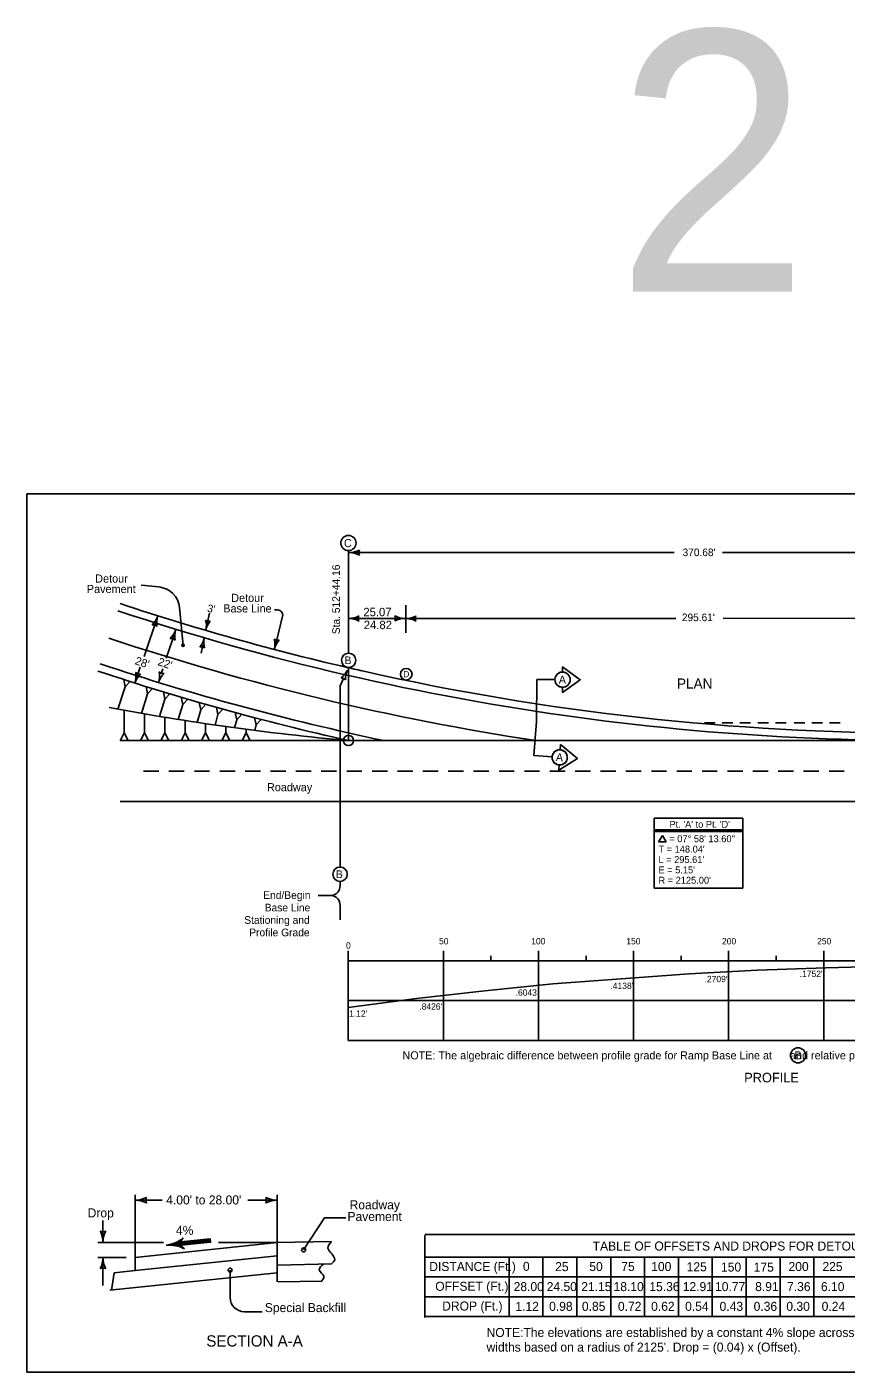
# Model space of a CAD drawing. Extents: x 10133 to 81668, y 4099 to 11018.
# Drawn here: x 13733 to 15616, y 7924 to 11018 of the extents above; entities that cross this region are included whole.
import ezdxf

# ---------------------------------------------------------------- set-up
doc = ezdxf.new("R2010")
doc.units = 0
for name, color, linetype in [('Default', 7, 'Continuous'), ('dsnCellElements', 7, 'Continuous'), ('Level 1', 7, 'Continuous'), ('Level 10', 7, 'Continuous'), ('Level 12', 7, 'Continuous'), ('Level 4', 7, 'Continuous'), ('Level 5', 7, 'Continuous'), ('SheetAddendum', 7, 'Continuous'), ('SheetBorder', 7, 'Continuous'), ('SheetText', 7, 'Continuous'), ('ShtPlotIdentification', 7, 'Continuous')]:
    doc.layers.add(name, color=color, linetype=linetype)

msp = doc.modelspace()

# ---------------------------------------------------------------- linework, layer by layer
at = {"layer": 'Default'}
for p, q in [((14471.7, 9376.6), (14471.7, 9544.2)), ((14471.7, 9544.2), (14471.7, 9376.6)), ((14471.7, 9376.6), (16078.7, 9376.6)), ((14471.7, 9376.6), (16078.7, 9376.6))]:
    msp.add_line(p, q, dxfattribs=at)
for centre, radius, start, end in [((15786.9, 15230.7), 5836.7, 251.62748, 257.33821), ((15786.9, 15230.7), 5854, 251.62748, 272.85748), ((15786.9, 15230.7), 5920.4, 251.62748, 261.4196), ((15786.9, 15230.7), 6000.1, 251.62748, 257.33821), ((15786.9, 15230.7), 5982.7, 251.62748, 258.10097), ((15786.9, 15230.7), 5836.7, 256.97753, 257.33821), ((15786.9, 15230.7), 5836.7, 257.33821, 270), ((15786.9, 15230.7), 5836.7, 257.33821, 270), ((15002.9, 15258.6), 5905.9, 259.45431, 264.83954)]:
    msp.add_arc(centre, radius, start, end, dxfattribs=at)
at = {"layer": 'dsnCellElements'}
for p, q in [((16087.1, 8240.2), (14647.3, 8240.2)), ((14647.3, 8237.9), (14647.3, 8049.7)), ((16087.1, 8188.2), (14647.3, 8188.2)), ((14841.2, 8188.2), (14841.2, 8052)), ((14919, 8188.2), (14919, 8188.2)), ((14919, 8188.2), (14919, 8052)), ((14919.3, 8188.2), (14919.3, 8188.2)), ((14919.4, 8188.2), (14919.4, 8188.2)), ((14919.6, 8188.2), (14919.6, 8188.2)), ((14996.9, 8188.2), (14996.9, 8052)), ((14996.9, 8188.2), (14996.9, 8188.2)), ((14996.9, 8188.2), (14996.9, 8052)), ((14997.1, 8188.2), (14997.1, 8188.2)), ((14997.3, 8188.2), (14997.3, 8188.2)), ((14997.5, 8188.2), (14997.5, 8188.2)), ((15074.8, 8188.2), (15074.8, 8052)), ((15152.7, 8188.2), (15152.7, 8052)), ((15230.5, 8188.2), (15230.5, 8052)), ((15308.4, 8188.2), (15308.4, 8052)), ((15386.3, 8188.2), (15386.3, 8052)), ((15464.1, 8188.2), (15464.1, 8052)), ((15542, 8188.2), (15542, 8052)), ((16087.1, 8142.8), (14647.3, 8142.8)), ((16087.1, 8097.4), (14647.3, 8097.4)), ((16087.1, 8052), (14647.3, 8052))]:
    msp.add_line(p, q, dxfattribs=at)
at = {"layer": 'Level 1'}
for p, q in [((13941.9, 9448.7), (13958.3, 9500.2)), ((13958.3, 9500.2), (13955.5, 9517)), ((13958.3, 9500.2), (13970.3, 9512.2)), ((14009.7, 9484.1), (14006.7, 9500.8)), ((13995.8, 9439.1), (14009.7, 9484.1)), ((14009.7, 9484.1), (14021.6, 9496.2)), ((14037.7, 9432), (14049.7, 9471.9)), ((14049.7, 9471.9), (14046.6, 9488.6)), ((14049.7, 9471.9), (14061.5, 9484.1)), ((14090.7, 9459.6), (14087.5, 9476.3)), ((14090.7, 9459.6), (14102.5, 9471.9)), ((13956.3, 9446.1), (13956.3, 9394.5)), ((14003, 9437.9), (14003, 9394.5)), ((14080.6, 9425.1), (14090.7, 9459.6)), ((14123.9, 9418.4), (14132.2, 9447.6)), ((14132.2, 9447.6), (14128.9, 9464.3)), ((14132.2, 9447.6), (14143.9, 9460)), ((14171.8, 9436.4), (14168.3, 9453.1)), ((14171.8, 9436.4), (14183.3, 9448.9)), ((14214.8, 9424.6), (14211.3, 9441.2)), ((14214.8, 9424.6), (14226.3, 9437.1)), ((14049.7, 9430.1), (14049.7, 9394.5)), ((14096.4, 9422.6), (14096.4, 9394.5)), ((14143.1, 9415.5), (14143.1, 9394.5)), ((14165, 9412.4), (14171.8, 9436.4)), ((14189.8, 9408.9), (14189.8, 9394.5)), ((14209.8, 9406.1), (14214.8, 9424.6)), ((14259.6, 9412.7), (14255.9, 9429.3)), ((14256.3, 9400), (14259.6, 9412.7)), ((14259.6, 9412.7), (14271, 9425.3)), ((13956.3, 9394.5), (13946.7, 9376)), ((13956.3, 9394.5), (13965.6, 9376.6)), ((14003, 9394.5), (13993.7, 9376.6)), ((14003, 9394.5), (14012.3, 9376.6)), ((14049.7, 9394.5), (14040.4, 9376.6)), ((14049.7, 9394.5), (14059, 9376.6)), ((14096.4, 9394.5), (14086.8, 9376)), ((14096.4, 9394.5), (14105.7, 9376.6)), ((14143.1, 9394.5), (14133.8, 9376.6)), ((14143.1, 9394.5), (14152.4, 9376.6)), ((14189.8, 9394.5), (14180.5, 9376.6)), ((14189.8, 9394.5), (14199, 9376.6)), ((14236.5, 9394.5), (14227.2, 9376.6)), ((14236.5, 9402.6), (14236.5, 9394.5)), ((14236.5, 9394.5), (14245.7, 9376.6))]:
    msp.add_line(p, q, dxfattribs=at)
at = {"layer": 'Level 10'}
for p, q in [((14471.7, 9577.7), (14471.7, 9813.5)), ((14309, 9677.2), (14301.8, 9677.2)), ((14301.8, 9586.2), (14320.3, 9662.8)), ((14471.7, 9544.2), (14471.7, 9544.7)), ((14452.5, 9502.4), (14460.5, 9519.2)), ((14452.5, 9502.4), (14452.5, 9085.7)), ((15174.7, 9198), (15174.7, 9037.3)), ((15174.7, 9198), (15378.3, 9198)), ((15378.3, 9037.3), (15378.3, 9198)), ((15174.7, 9171), (15378.3, 9171)), ((15174.7, 9167.1), (15378.3, 9167.1)), ((15184.6, 9143.4), (15193.6, 9158.3)), ((15202.5, 9143.4), (15184.6, 9143.4)), ((15193.6, 9158.3), (15202.5, 9143.4)), ((14452.5, 9043.5), (14452.5, 9052.7)), ((15174.7, 9037.3), (15378.3, 9037.3)), ((14402.5, 9020.3), (14432.1, 9020.3)), ((14452.5, 8997.1), (14452.5, 8964.5)), ((13981.3, 8187.9), (13981.3, 8331.9)), ((14308.1, 8222.1), (14308.1, 8331.9)), ((14199.8, 8158.5), (14199.8, 8095.4)), ((14273.7, 8062.9), (14232.3, 8062.9))]:
    msp.add_line(p, q, dxfattribs=at)
for centre, radius in [((14471.7, 9831), 17.5), ((14091.5, 9595.6), 2.42), ((14091.5, 9595.6), 2.05), ((14091.5, 9595.6), 1.71), ((14091.5, 9595.6), 1.32), ((14091.5, 9595.6), 1.05), ((14091.5, 9595.6), 0.874), ((14091.5, 9595.6), 0.683), ((14091.5, 9595.6), 0.505), ((14091.5, 9595.6), 0.313), ((14091.5, 9595.6), 0.149), ((14472.3, 9561.2), 16.5), ((14604.6, 9529.3), 13.4), ((14471.7, 9376.6), 11.7), ((14452.5, 9069.2), 16.5)]:
    msp.add_circle(centre, radius, dxfattribs=at)
for centre, radius, start, end in [((14309, 9665.5), 11.7, 346.4041, 90), ((14152.2, 9669.3), 18.1, 240.459, 275.9257), ((14098.4, 9640.5), 46.8, 348.1924, 16.2649), ((14189.9, 9621.4), 46.8, 140.1199, 168.1924), ((14094.5, 9621.9), 46.8, 320.1199, 348.1924), ((14132.2, 9573.9), 18.1, 60.459, 95.9257), ((14186, 9602.7), 46.8, 168.1924, 196.2649), ((14310.5, 9626.8), 19.2, 240.2469, 275.7136), ((14253.3, 9596.5), 49.6, 347.9802, 16.0527), ((14350.3, 9575.8), 49.6, 139.9077, 167.9802), ((14426.8, 9559), 47.3, 306.4802, 334.5527), ((14512.3, 9518.3), 47.3, 154.5527, 182.6252), ((14452.5, 9502.8), 18.3, 46.8193, 82.286), ((14430.5, 9042.3), 22, 274.0563, 3.2919), ((14430.5, 8998.4), 22, 356.7081, 85.9437), ((14232.3, 8095.4), 32.4, 180, 270)]:
    msp.add_arc(centre, radius, start, end, dxfattribs=at)
at = {"layer": 'Level 12'}
for centre in [(14368.8, 8205.1), (14199.8, 8158.5)]:
    msp.add_circle(centre, 4.6, dxfattribs=at)
at = {"layer": 'Level 4'}
for p, q in [((14904.6, 9517.1), (14903.9, 9420.4)), ((14904.6, 9517.1), (14946.6, 9516.8)), ((14903.9, 9420.4), (14898.1, 9342.4)), ((14898.1, 9342.4), (14940, 9339.3))]:
    msp.add_line(p, q, dxfattribs=at)
for points in [[(14964.2, 9534.2), (14964.3, 9545.9), (15004.9, 9516.4), (14963.9, 9487.5), (14964, 9499.2)], [(14964.2, 9534.2), (14964.2, 9534.2), (14964.2, 9534.2)], [(14958.8, 9355.5), (14959.7, 9367.2), (14998.3, 9335), (14955.4, 9308.9), (14956.2, 9320.6)], [(14958.8, 9355.5), (14958.8, 9355.5), (14958.8, 9355.5)]]:
    msp.add_lwpolyline(points, dxfattribs=at)
for centre, radius in [((14964.1, 9516.7), 17.5), ((14957.5, 9338), 17.5), ((15505.5, 8652.6), 17.4)]:
    msp.add_circle(centre, radius, dxfattribs=at)
for centre, start, end in [((14964.1, 9516.7), 89.5971, 269.5988), ((14964.1, 9516.7), 269.5988, 89.5971), ((14957.5, 9338), 85.783, 265.7846), ((14957.5, 9338), 265.7846, 85.783)]:
    msp.add_arc(centre, 17.5, start, end, dxfattribs=at)
at = {"layer": 'Level 5'}
for p, q in [((15314.7, 9417.3), (15290.2, 9417.3)), ((15355.5, 9417.3), (15331, 9417.3)), ((15396.4, 9417.3), (15371.9, 9417.3)), ((15437.2, 9417.3), (15412.7, 9417.3)), ((15478.1, 9417.3), (15453.6, 9417.3)), ((15520.9, 9417.4), (15496.4, 9417.4)), ((15561.7, 9417.4), (15537.2, 9417.4)), ((15602.6, 9417.4), (15578.1, 9417.4)), ((14455.2, 9376.6), (13946.7, 9376.6)), ((14035.9, 9306.5), (14000.8, 9306.5)), ((14094.2, 9306.5), (14059.2, 9306.5)), ((14152.6, 9306.5), (14117.6, 9306.5)), ((14211, 9306.5), (14175.9, 9306.5)), ((14269.3, 9306.5), (14234.3, 9306.5)), ((14327.7, 9306.5), (14292.7, 9306.5)), ((14386.1, 9306.5), (14351, 9306.5)), ((14444.4, 9306.5), (14409.4, 9306.5)), ((14502.8, 9306.5), (14467.8, 9306.5)), ((14561.2, 9306.5), (14526.1, 9306.5)), ((14619.5, 9306.5), (14584.5, 9306.5)), ((14677.9, 9306.5), (14642.9, 9306.5)), ((14736.3, 9306.5), (14701.2, 9306.5)), ((14794.6, 9306.5), (14759.6, 9306.5)), ((14853, 9306.5), (14818, 9306.5)), ((14911.4, 9306.5), (14876.3, 9306.5)), ((14969.7, 9306.5), (14934.7, 9306.5)), ((15028.1, 9306.5), (14993.1, 9306.5)), ((15086.5, 9306.5), (15051.4, 9306.5)), ((15144.8, 9306.5), (15109.8, 9306.5)), ((15203.2, 9306.5), (15168.2, 9306.5)), ((15261.6, 9306.5), (15226.5, 9306.5)), ((15319.9, 9306.5), (15284.9, 9306.5)), ((15378.3, 9306.5), (15343.3, 9306.5)), ((15436.7, 9306.5), (15401.6, 9306.5)), ((15495, 9306.5), (15460, 9306.5)), ((15553.4, 9306.5), (15518.4, 9306.5)), ((15611.8, 9306.5), (15576.7, 9306.5)), ((16078.7, 9236.5), (13947, 9236.5)), ((14471.5, 8687.1), (14471.5, 8892.7)), ((14690.1, 8869.9), (14690.1, 8892.7)), ((14799.4, 8869.9), (14799.4, 8881.3)), ((14908.7, 8687.1), (14908.7, 8892.7)), ((15018, 8869.9), (15018, 8881.3)), ((15127.3, 8687.1), (15127.3, 8892.7)), ((15236.6, 8869.9), (15236.6, 8881.3)), ((15345.9, 8687.1), (15345.9, 8892.7)), ((15455.2, 8869.9), (15455.2, 8881.3)), ((15564.5, 8687.1), (15564.5, 8892.7)), ((14471.5, 8869.9), (16220.3, 8869.9)), ((14690.1, 8869.9), (14690.1, 8687.1)), ((15569.1, 8853.9), (15412.3, 8848.3)), ((15725.9, 8857.6), (15569.1, 8853.9)), ((14941.9, 8816.8), (15098.7, 8828.9)), ((15098.7, 8828.9), (15255.5, 8840)), ((15255.5, 8840), (15412.3, 8848.3)), ((14628.3, 8783.4), (14785.1, 8801)), ((14785.1, 8801), (14941.9, 8816.8)), ((14471.5, 8763), (14628.3, 8783.4)), ((16220.3, 8778.5), (14471.5, 8778.5)), ((14471.5, 8687.1), (16220.3, 8687.1)), ((14368.8, 8205.1), (14416.5, 8279)), ((14416.5, 8279), (14466, 8279)), ((14308.1, 8222.1), (13981.3, 8187.9)), ((14432.7, 8224.6), (14308.1, 8222.1)), ((14308.1, 8131.3), (14308.1, 8222.1)), ((13981.3, 8157.6), (14308.1, 8191.8)), ((13981.3, 8187.9), (13981.3, 8157.6)), ((14432.6, 8172.7), (14309.1, 8170.2)), ((14308.1, 8152.7), (13923.3, 8112.4)), ((13933.1, 8152.6), (13926.8, 8112.8)), ((13981.3, 8157.6), (13933.1, 8152.6)), ((14410.3, 8133.3), (14309.9, 8131.3))]:
    msp.add_line(p, q, dxfattribs=at)
msp.add_lwpolyline([(14308.1, 8222.1), (13981.3, 8187.9), (13981.3, 8157.6), (14308.1, 8191.8)], close=True, dxfattribs=at)
for points in [[(14432.7, 8224.6), (14424.6, 8209.4), (14440.3, 8183), (14432.6, 8172.7)], [(14410.3, 8133.3), (14415.3, 8143.7), (14404.6, 8159.4), (14414.6, 8172.2)]]:
    msp.add_spline(points, degree=3, dxfattribs=at)
at = {"layer": 'SheetAddendum'}
for p, q in [((15221, 9808.9), (14472.9, 9808.9)), ((15331.7, 9808.9), (16079.7, 9808.9)), ((14036.2, 9729.9), (13995.2, 9734.1)), ((14603.7, 9624.8), (14603.7, 9688.1)), ((14001.8, 9570), (14033.3, 9663.4)), ((14091.5, 9595.6), (14083.4, 9682.4)), ((14152.2, 9669.4), (14144.2, 9631)), ((14536.2, 9657.4), (14472.4, 9657.4)), ((14601.5, 9657.6), (14536.2, 9657.4)), ((15224.4, 9657.2), (14606.5, 9657.3)), ((15333.2, 9657.6), (15786.1, 9657.9)), ((14052.8, 9565.8), (14073, 9626.3)), ((14132.9, 9577.7), (14136.9, 9596.3)), ((13980.8, 9508.9), (13992.7, 9545.7)), ((14041.3, 9529.7), (14045.2, 9541.6)), ((14043.2, 8319.4), (13981.3, 8319.4)), ((14308.1, 8319.4), (14240.5, 8319.4)), ((13907.3, 8222.1), (13907.3, 8273)), ((14046.7, 8222.1), (13895.4, 8222.1)), ((14086.7, 8223.6), (14086.7, 8223.6)), ((14086.9, 8219.4), (14154.4, 8226.5)), ((14087.5, 8215.6), (14087.5, 8215.6)), ((14307.7, 8222.1), (14173, 8222.1)), ((13961.1, 8187.9), (13895.4, 8187.9)), ((13907.3, 8123.4), (13907.3, 8187.9))]:
    msp.add_line(p, q, dxfattribs=at)
for points in [[(14088, 8228.5), (14085.6, 8223.6), (14086, 8216.8), (14089, 8211.2), (14078.6, 8214.3), (14066.6, 8216.5), (14063.3, 8217), (14071.5, 8219.5), (14083.3, 8225.1), (14086.7, 8227.5), (14086.9, 8212.9), (14068.3, 8217.2), (14085.2, 8224.4), (14085.6, 8214.4), (14072.8, 8217.8), (14083.8, 8221.8), (14084.9, 8216.1), (14076.8, 8217.9), (14082.6, 8220.2), (14083.2, 8217.5), (14080.3, 8218)], [(14086.7, 8223.3), (14154, 8230.3), (14154.8, 8222.6), (14087.5, 8215.6), (14087, 8222.2), (14153.2, 8229.4), (14153.7, 8223.2), (14088.9, 8216.7), (14088.2, 8221.3), (14152.4, 8228.3), (14152.7, 8224.1), (14089.6, 8217.6), (14089.2, 8220.4), (14151.7, 8227.3), (14151.9, 8225), (14090.4, 8218.7)]]:
    msp.add_lwpolyline(points, dxfattribs=at)
for centre, radius, start, end in [((14473, 9859.8), 50.9, 270, 298.0725), ((14473, 9758), 50.9, 61.9275, 90), ((14515.6, 9808.9), 19.7, 162.2666, 197.7334), ((14030.9, 9677.4), 52.8, 5.3657, 84.2172), ((13986.1, 9678.9), 49.6, 313.6652, 341.7377), ((14080.4, 9647.8), 49.6, 161.7377, 189.8102), ((14472.4, 9707), 49.6, 270, 298.0725), ((14472.4, 9607.8), 49.6, 61.9275, 90), ((14514, 9657.4), 19.2, 162.2666, 197.7334), ((14559.9, 9657.6), 19.2, 342.2666, 17.7333), ((14601.5, 9707.2), 49.6, 241.9275, 270), ((14601.5, 9608), 49.6, 90, 118.0725), ((14603.7, 9706.9), 49.6, 270, 298.0725), ((14603.7, 9607.7), 49.6, 61.9275, 90), ((14645.3, 9657.3), 19.2, 162.2666, 197.7334), ((14020.2, 9623.9), 19.2, 54.0044, 89.4711), ((14027.7, 9647.4), 49.6, 313.6652, 341.7377), ((14122, 9616.3), 49.6, 161.7377, 189.8102), ((14061.8, 9592.4), 19.2, 54.0044, 89.4711), ((13933.7, 9524.5), 49.6, 341.7377, 9.8102), ((13993.8, 9548.4), 19.2, 234.0044, 269.4711), ((13987.9, 9526.1), 49.6, 341.7377, 9.8102), ((14082.1, 9495), 49.6, 133.6652, 161.7377), ((14048, 9550.1), 19.2, 234.0044, 269.4711), ((14027.9, 9493.4), 49.6, 133.6652, 161.7377), ((13981.3, 8374.6), 55.2, 270, 298.0725), ((14027.5, 8319.4), 21.3, 162.2666, 197.7334), ((14261.8, 8319.4), 21.3, 342.2667, 17.7334), ((14308.1, 8374.6), 55.2, 241.9275, 270), ((13981.3, 8264.3), 55.2, 61.9275, 90), ((14308.1, 8264.3), 55.2, 90, 118.0725), ((13907.3, 8268.3), 21.3, 252.2667, 287.7334), ((13852.2, 8222.1), 55.2, 0, 28.0725), ((13962.5, 8222.1), 55.2, 151.9275, 180), ((13852.2, 8187.9), 55.2, 331.9275, 0), ((13962.5, 8187.9), 55.2, 180, 208.0725), ((13907.3, 8141.7), 21.3, 72.2666, 107.7334)]:
    msp.add_arc(centre, radius, start, end, dxfattribs=at)
for centre, major_axis, start_param, end_param in [((14041.6, 8298.8), (8.7, -83.2), 0.029395, 0.553518), ((14100.9, 8220.9), (-1.5, 14.6), 0.553526, 2.588067), ((14059, 8132.4), (8.7, -83.2), 2.588074, 3.112197)]:
    msp.add_ellipse(centre, major_axis=major_axis, ratio=0.985299, start_param=start_param, end_param=end_param, dxfattribs=at)
at = {"layer": 'SheetBorder'}
msp.add_lwpolyline([(13732.5, 9944), (16867.5, 9944), (16867.5, 7924), (13732.5, 7924)], close=True, dxfattribs=at)
at = {"layer": 'ShtPlotIdentification'}
msp.add_line((14471.7, 9376.6), (14455.2, 9376.6), dxfattribs=at)

# ---------------------------------------------------------------- texts
at = {"layer": 'dsnCellElements'}
for s, height, p in [('TABLE OF OFFSETS AND DROPS FOR DETOUR PAVEMENT', 20.766, (15033.3, 8203.6)), ('DISTANCE (Ft.)', 20.766, (14657.6, 8156.5)), ('0', 20.7, (14873, 8156.9)), ('25', 20.75, (14947, 8156.2)), ('50', 20.75, (15025.6, 8156.5)), ('75', 20.75, (15099.1, 8156.5)), ('100', 20.75, (15167.9, 8156.5)), ('125', 20.75, (15249.4, 8155.9)), ('150', 20.75, (15328.4, 8155.3)), ('175', 20.75, (15403.5, 8155.1)), ('200', 20.75, (15483.6, 8156.5)), ('225', 20.75, (15561.6, 8156.5)), ('OFFSET (Ft.)', 20.766, (14671.4, 8111)), ('28.00', 20.75, (14851.6, 8110.3)), ('24.50', 20.75, (14927.6, 8110.3)), ('21.15', 20.75, (15007.1, 8110.3)), ('18.10', 20.75, (15081.3, 8110.3)), ('15.36', 20.75, (15163.6, 8110.3)), ('12.91', 20.75, (15240.4, 8110.3)), ('10.77', 20.75, (15314.7, 8110.3)), ('8.91', 20.75, (15406.9, 8110.3)), ('7.36', 20.75, (15480.2, 8110.3)), ('6.10', 20.75, (15558.2, 8110.3)), ('DROP (Ft.)', 20.77, (14687.3, 8065.6)), ('1.12', 20.75, (14855.6, 8064.8)), ('0.98', 20.75, (14933.2, 8064.9)), ('0.85', 20.75, (15008.6, 8064.9)), ('0.72', 20.75, (15091.4, 8064.9)), ('0.62', 20.75, (15167.7, 8064.9)), ('0.54', 20.75, (15245.9, 8064.9)), ('0.43', 20.75, (15325.1, 8064.9)), ('0.36', 20.75, (15403.4, 8064.9)), ('0.30', 20.75, (15478.6, 8064.9)), ('0.24', 20.75, (15559.8, 8064.9))]:
    msp.add_text(s, height=height, dxfattribs=at).set_placement(p)
at = {"layer": 'Level 10'}
for s, height, p in [('C', 18.7, (14461.5, 9821.6)), ("370.68'", 17.43, (15240, 9800.8)), ('Detour ', 18.68, (13889.5, 9740)), ('Pavement', 18.68, (13870.2, 9715.9)), ('Base Line', 18.68, (14184, 9671.3)), ('Detour', 18.68, (14202.2, 9695.5)), ('25.07', 19.36, (14506.1, 9662.6)), ("295.61'", 17.42, (15238.4, 9651.3)), ('24.82', 19.36, (14507, 9632.9)), ('B', 17.6, (14463, 9552.4)), ('D', 14.3, (14598, 9522.2)), ('PLAN', 23.35, (15227.1, 9496.1)), ('Roadway               ', 18.677, (14284.4, 9260.1)), ("Pt. 'A' to Pt. 'D'", 15.889, (15209.9, 9176)), ("= 07° 58' 13.60''", 15.889, (15209.5, 9142.9)), ("T = 148.04'", 15.889, (15184.6, 9118.9)), ("L = 295.61'", 15.889, (15184.6, 9095)), ('B', 17.6, (14443.1, 9060.4)), ("E = 5.15'", 15.89, (15184.6, 9071.2)), ("R = 2125.00'", 15.889, (15184.6, 9047.4)), ('End/Begin', 17.6, (14275.9, 9012.3)), ('Stationing and', 17.603, (14232.2, 8955.1)), ('Base Line', 17.6, (14279.3, 8983.7)), ('Profile Grade', 17.603, (14243.8, 8926.5)), ('0', 14.6, (14466.3, 8898)), ('50', 14.62, (14680.1, 8907.8)), ('100', 14.62, (14892, 8907.8)), ('150', 14.62, (15110.6, 8907.8)), ('200', 14.62, (15330.7, 8907.8)), ('250', 14.62, (15549.3, 8907.8)), (".4138'", 14.62, (15074.1, 8805.2)), (".2709'", 14.62, (15290.6, 8820.8)), (".1752'", 14.62, (15509.3, 8832.9)), ('.6043', 14.62, (14856.1, 8789.9)), (".8426'", 14.62, (14634.7, 8757.7)), ("1.12'", 14.62, (14473.2, 8741.2)), ('NOTE: The algebraic difference between profile grade for Ramp Base Line at      and relative profile grade of Mainline at      is 0.32%. ', 18.5883, (14595.9, 8643.3)), ('B', 18.6, (15497.5, 8643.3)), ('PROFILE', 22, (15381.7, 8590.4)), ('Pavement', 20.77, (14469.5, 8271.6)), ('Roadway', 20.77, (14474.4, 8298.5)), ('Special Backfill', 20.766, (14279.5, 8062)), ('NOTE:The elevations are established by a constant 4% slope across the appropriate detour', 20.766, (14789.3, 8004.8)), ("widths based on a radius of 2125'. Drop = (0.04) x (Offset).", 20.766, (14789.3, 7971.1))]:
    msp.add_text(s, height=height, dxfattribs=at).set_placement(p)
for s, height, rotation, p in [('Sta. 512+44.16', 17.603, 90, (14452.1, 9621.2)), ("3'", 17.6, 348.1924, (14146, 9673.2)), ("28'", 18.68, 341.7377, (13979.4, 9552.5)), ("22'", 18.68, 341.7377, (14031.9, 9550.5))]:
    msp.add_text(s, height=height, rotation=rotation, dxfattribs=at).set_placement(p)
at = {"layer": 'Level 4'}
for rotation, p in [(359.5979, (14955.3, 9507.4)), (355.7838, (14948.1, 9329.4))]:
    msp.add_text('A', height=18.7, rotation=rotation, dxfattribs=at).set_placement(p)
msp.add_text('SECTION A-A', height=25.957, dxfattribs=at).set_placement((14145, 7982.7))
at = {"layer": 'SheetAddendum'}
for s, height, p in [("4.00' to 28.00'", 20.766, (14052.8, 8309.7)), ('Drop', 20.77, (13872.1, 8279.8)), ('4%', 20.77, (14075.2, 8239.7))]:
    msp.add_text(s, height=height, dxfattribs=at).set_placement(p)
at = {"layer": 'SheetText'}
msp.add_text('2', height=600, dxfattribs=at).set_placement((15085.9, 10409.2))

doc.saveas('drawing.dxf')
